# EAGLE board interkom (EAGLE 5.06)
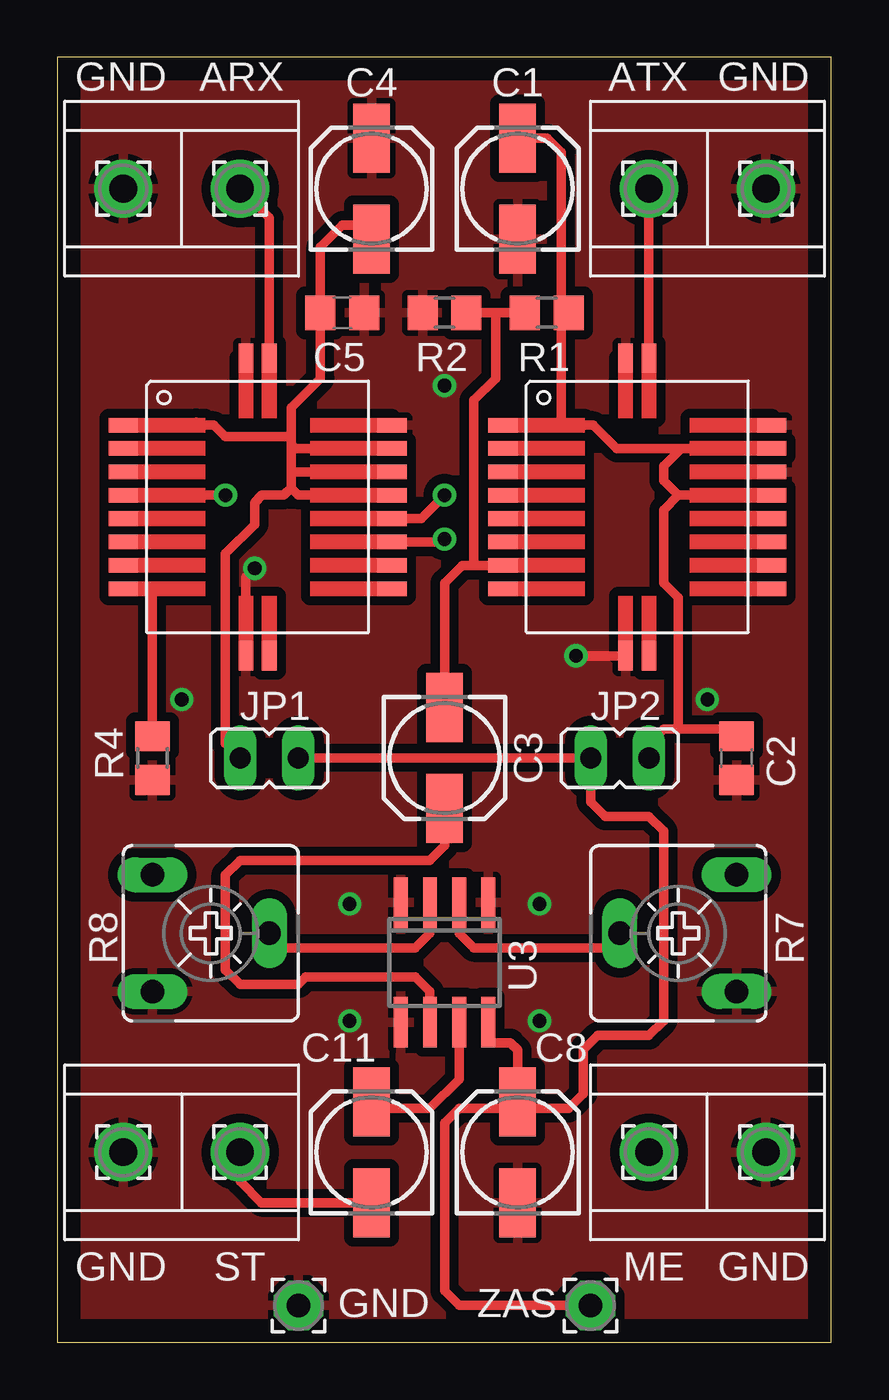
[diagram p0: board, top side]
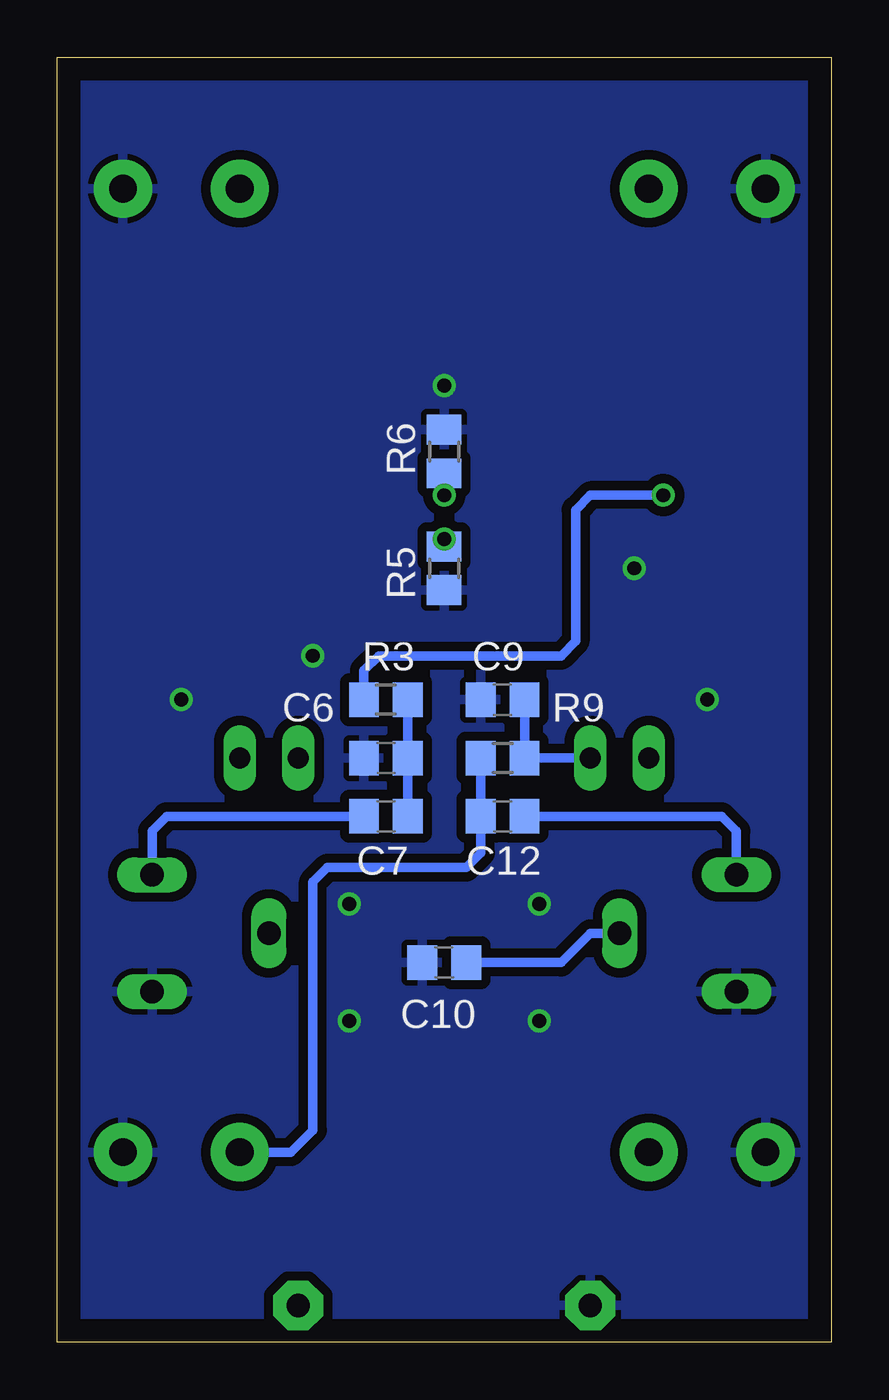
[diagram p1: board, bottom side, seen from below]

Size 33.64 x 55.87 mm. Coordinates in mm from the lower left corner, seen from the top.
Outline: 0,0 33.64,0 33.64,55.87 0,55.87 0,0
Copper layers (1*16): Top 0.035mm / dielectric 1.5mm / Bottom 0.035mm
Design rules "default": minimum track width 10mil, minimum drill 24mil, track to track 8mil, track to pad 8mil, pad to pad 8mil, via to via 8mil, smd to smd 8mil, copper to edge 40mil, drill to drill 8mil, minimum pad ring 10mil, minimum via ring 8mil, stop-mask expansion 4mil, vias tented up to drill 0mil, thermal gap 10mil

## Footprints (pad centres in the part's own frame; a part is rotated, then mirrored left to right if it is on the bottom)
2,15/1,0 = drill 1.016 pad 2.159 octagon: 1 0,0
153CLV-0505 = smd 3 x 1.6: + 2.2,0; - -2.2,0
C0805 = smd 1.3 x 1.5: 1 -0.95,0; 2 0.95,0
JP1 = drill 0.914 long: 1 0,-1.27; 2 0,1.27
R0805 = smd 1.3 x 1.5: 1 -0.95,0; 2 0.95,0
CA6V = drill 1.016 long: A -2.54,-2.54; E 2.54,-2.54; S 0,2.54
TXRX = smd 0.635 x 1.27: P$1 -0.381,6.604; P$10 -0.381,-6.35; P$11 0.635,-6.35; P$20 0.635,6.604 | smd 1.27 x 0.635: P$2 -5.715,3.683; P$3 -5.715,2.667; P$4 -5.715,1.651; P$5 -5.715,0.635; P$6 -5.715,-0.381; P$7 -5.715,-1.397; P$8 -5.715,-2.413; P$9 -5.715,-3.429; P$12 5.969,-3.429; P$13 5.969,-2.413; P$14 5.969,-1.397; P$15 5.969,-0.381; P$16 5.969,0.635; P$17 5.969,1.651; P$18 5.969,2.667; P$19 5.969,3.683
SO08 = smd 0.6 x 2.2: 1 -1.905,-2.6; 2 -0.635,-2.6; 3 0.635,-2.6; 4 1.905,-2.6; 5 1.905,2.6; 6 0.635,2.6; 7 -0.635,2.6; 8 -1.905,2.6
ARK2 = drill 1.2 pad 2.54 round: P$3 -2.54,0; P$4 2.54,0

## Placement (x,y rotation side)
ARX  [2,15/1,0]  7.94,50.16 0 top
ARX_GND  [2,15/1,0]  2.86,50.16 270 top
ATX  [2,15/1,0]  25.72,50.16 0 top
ATX_GND  [2,15/1,0]  30.8,50.16 270 top
C1  [153CLV-0505]  20,50.16 90 top
C2  [C0805]  29.53,25.4 90 top
C3  [153CLV-0505]  16.83,25.4 270 top
C4  [153CLV-0505]  13.65,50.16 90 top
C5  [C0805]  12.38,44.77 180 top
C6  [C0805]  19.37,25.4 0 bottom
C7  [C0805]  19.37,22.86 0 bottom
C8  [153CLV-0505]  20,8.25 90 top
C9  [C0805]  14.29,27.94 180 bottom
C10  [C0805]  16.83,16.51 180 bottom
C11  [153CLV-0505]  13.65,8.25 90 top
C12  [C0805]  14.29,22.86 0 bottom
GND  [2,15/1,0]  10.48,1.59 0 top
JP1  [JP1]  9.21,25.4 270 top
JP2  [JP1]  24.45,25.4 90 top
ME  [2,15/1,0]  25.72,8.25 0 top
ME_GND  [2,15/1,0]  30.8,8.25 270 top
R1  [R0805]  21.27,44.77 0 top
R2  [R0805]  16.83,44.77 0 top
R3  [R0805]  19.37,27.94 180 bottom
R4  [R0805]  4.13,25.4 90 top
R5  [R0805]  16.83,33.66 270 bottom
R6  [R0805]  16.83,38.73 90 bottom
R7  [CA6V]  26.99,17.78 90 top
R8  [CA6V]  6.67,17.78 270 top
R9  [R0805]  14.29,25.4 180 bottom
ST  [2,15/1,0]  7.94,8.25 0 top
ST_GND  [2,15/1,0]  2.86,8.25 270 top
U1  TXRX  [TXRX]  25.08,36.2 0 top
U2  TXRX  [TXRX]  8.57,36.2 0 top
U3  SOO8  [SO08]  16.83,16.51 180 top
U$4  ARK2  [ARK2]  28.26,50.16 180 top
U$5  ARK2  [ARK2]  5.4,8.25 180 top
U$7  ARK2  [ARK2]  28.26,8.25 0 top
U$8  ARK2  [ARK2]  5.4,50.16 0 top
ZAS  [2,15/1,0]  23.18,1.59 0 top

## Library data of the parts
ARX ARX_GND ATX ATX_GND GND ME ME_GND ST ST_GND ZAS = wirepad
C1-C12 R1-R6 R9 = rcl
JP1 JP2 = jumper
R7 R8 = pot
U1 U2 = TXRX
U3 = linear
U$4 U$5 U$7 U$8 = ark2_5mm

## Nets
GND: ARX_GND.1 ATX_GND.1 C1.- C2.1 C4.+ C5.1 C6.1 C8.- C9.2 C10.2 GND.1 ME_GND.1 R2.1 R4.1 R5.2 R6.2 R7.A R8.E ST_GND.1 U1.P$1 U1.P$10 U1.P$17 U1.P$19 U2.P$1 U2.P$10 U2.P$19 U3.1 U3.4 U3.5 U$4.P$3 U$5.P$4 U$7.P$4 U$8.P$3
N$1: C3.- R1.1 R2.2 U1.P$8
N$2: R5.1 U2.P$14
N$3: R6.1 U2.P$15
N$4: R3.2 U2.P$5
N$5: R4.2 U2.P$9
N$6: ATX.1 U1.P$20 U$4.P$4
N$7: C1.+ C2.2 JP2.1 R1.2 U1.P$2 U1.P$16 U1.P$18
N$9: ARX.1 U2.P$20 U$8.P$4
N$10: C6.2 C7.2 R3.1
N$11: C7.1 R7.E
N$12: R7.S U3.2
N$13: C10.1 R8.S U3.3
N$14: C12.2 R8.A
N$15: C8.+ C9.1 JP1.2 JP2.2 R9.1 U3.8 ZAS.1
N$16: C12.1 ME.1 R9.2 U$7.P$3
N$17: C3.+ U3.6
N$18: C11.+ U3.7
N$19: C11.- ST.1 U$5.P$3
N$20: C4.- C5.2 JP1.1 U2.P$2 U2.P$16 U2.P$17 U2.P$18

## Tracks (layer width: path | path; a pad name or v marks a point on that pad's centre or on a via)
GND  (via drill 0.6)
  Top 0.406: v22.54,29.84 U1.P$10 | U2.P$10 8.19,33.27 v8.57,33.66
  other vias: 16.83,41.59 5.4,27.94 12.7,13.97 20.96,13.97 28.26,27.94 20.96,19.05 12.7,19.05
  pour Bottom (isolate 0.406): -0.63,56.52 34.29,56.52 33.34,-0.63 -0.63,-0.63
  pour Top (isolate 0.406): -0.63,56.52 34.29,56.52 34.29,-0.63 -0.63,-0.63
N$1
  Top 0.406: 18.1,33.78 17.59,33.78 16.83,33.02 C3.- | 18.1,33.78 U1.P$8 | 19.05,44.77 R2.2 | 19.05,44.77 R1.1 | 18.1,33.78 18.1,40.96 19.05,41.91 19.05,44.77
N$2  (via drill 0.6)
  Top 0.406: U2.P$14 16.7,34.8 v16.83,34.92
  Bottom 0.406: v16.83,34.92 R5.1
N$3  (via drill 0.6)
  Top 0.406: U2.P$15 15.81,35.81 v16.83,36.83
  Bottom 0.406: v16.83,36.83 R6.1
N$4  (via drill 0.6)
  Top 0.406: U2.P$5 v7.3,36.83
  Bottom 0.406: v7.3,36.83 10.48,36.83 11.11,36.2 11.11,30.48 11.75,29.84 19.68,29.84 20.32,29.21 R3.2
N$5
  Top 0.406: U2.P$9 4.13,32.77 R4.2
N$6
  Top 0.406: U1.P$20 U$4.P$4
N$7
  Top 0.406: 29.53,26.03 C2.2 29.21,26.67 26.99,26.67 | JP2.1 25.72,26.03 26.35,26.67 26.99,26.67 | 27.11,38.86 U1.P$18 | 26.99,26.67 26.99,32.38 26.35,33.02 26.35,36.2 26.99,36.83 | 27.11,38.86 24.32,38.86 23.3,39.88 21.91,39.88 | 27.11,38.86 26.35,38.1 26.35,37.46 26.99,36.83 | 26.99,36.83 U1.P$16 | 21.91,39.88 U1.P$2 | C1.+ 21.29,52.37 21.91,51.75 21.91,44.77 | 21.91,44.77 R1.2 21.91,45.09 21.91,44.77 | 21.91,39.88 21.91,44.77
N$9
  Top 0.406: U2.P$20 9.21,48.89 U$8.P$4
N$10
  Bottom 0.406: R3.1 C6.2 C7.2
N$11
  Bottom 0.406: C7.1 28.89,22.86 29.53,22.22 R7.E
N$12
  Top 0.406: U3.2 17.46,17.78 18.1,17.14 23.81,17.14 R7.S
N$13
  Top 0.406: U3.3 16.19,17.78 15.56,17.14 9.84,17.14 R8.S
  Bottom 0.406: C10.1 15.88,16.82 C10.1 11.75,16.51 10.48,17.78 R8.S
N$14
  Bottom 0.406: C12.2 4.76,22.86 4.13,22.22 R8.A
N$15
  Top 0.406: C8.+ 20.64,10.16 22.23,10.16 22.86,10.79 22.86,12.7 23.49,13.34 25.72,13.34 26.35,13.97 26.35,22.22 25.72,22.86 23.81,22.86 23.18,23.49 JP2.2 JP1.2 | ZAS.1 17.46,1.59 16.83,2.22 16.83,9.52 17.46,10.16 20.3,10.16 C8.+ | C8.+ 20,12.7 19.68,13.02 18.73,13.02 U3.8
  Bottom 0.406: C9.1 R9.1 JP1.2
N$16
  Bottom 0.406: R9.2 C12.1 15.24,21.27 15.87,20.64 21.91,20.64 22.54,20 22.54,9.21 23.49,8.25 U$7.P$3
N$17
  Top 0.406: C3.+ 16.83,21.59 16.19,20.95 7.94,20.95 7.3,20.32 7.3,16.19 7.94,15.56 10.48,15.56 10.8,15.88 15.56,15.88 16.19,15.24 U3.6
N$18
  Top 0.406: U3.7 17.46,11.43 16.19,10.16 13.36,10.16 C11.+
N$19
  Top 0.406: C11.- 8.87,6.05 7.94,6.98 U$5.P$3
N$20
  Top 0.406: 5.91,39.88 U2.P$2 | 5.91,39.88 6.03,40.01 | 5.91,39.88 6.79,39.88 7.3,39.37 10.16,39.37 | JP1.1 7.3,26.03 7.3,34.29 8.57,35.56 8.57,36.51 8.89,36.83 9.84,36.83 10.16,37.15 | C4.- 13.63,48.58 12.38,48.58 11.43,47.63 C5.2 11.43,45.4 11.43,41.91 10.16,40.64 10.16,39.37 | 10.16,37.15 10.16,37.78 | 10.16,37.15 10.48,36.83 U2.P$16 | U2.P$17 10.22,37.85 10.16,37.78 | 10.16,37.78 10.16,39.05 | 10.16,39.05 10.16,39.37 | U2.P$18 10.35,38.86 10.16,39.05

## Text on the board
tPlace: GND | GND | GND | GND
